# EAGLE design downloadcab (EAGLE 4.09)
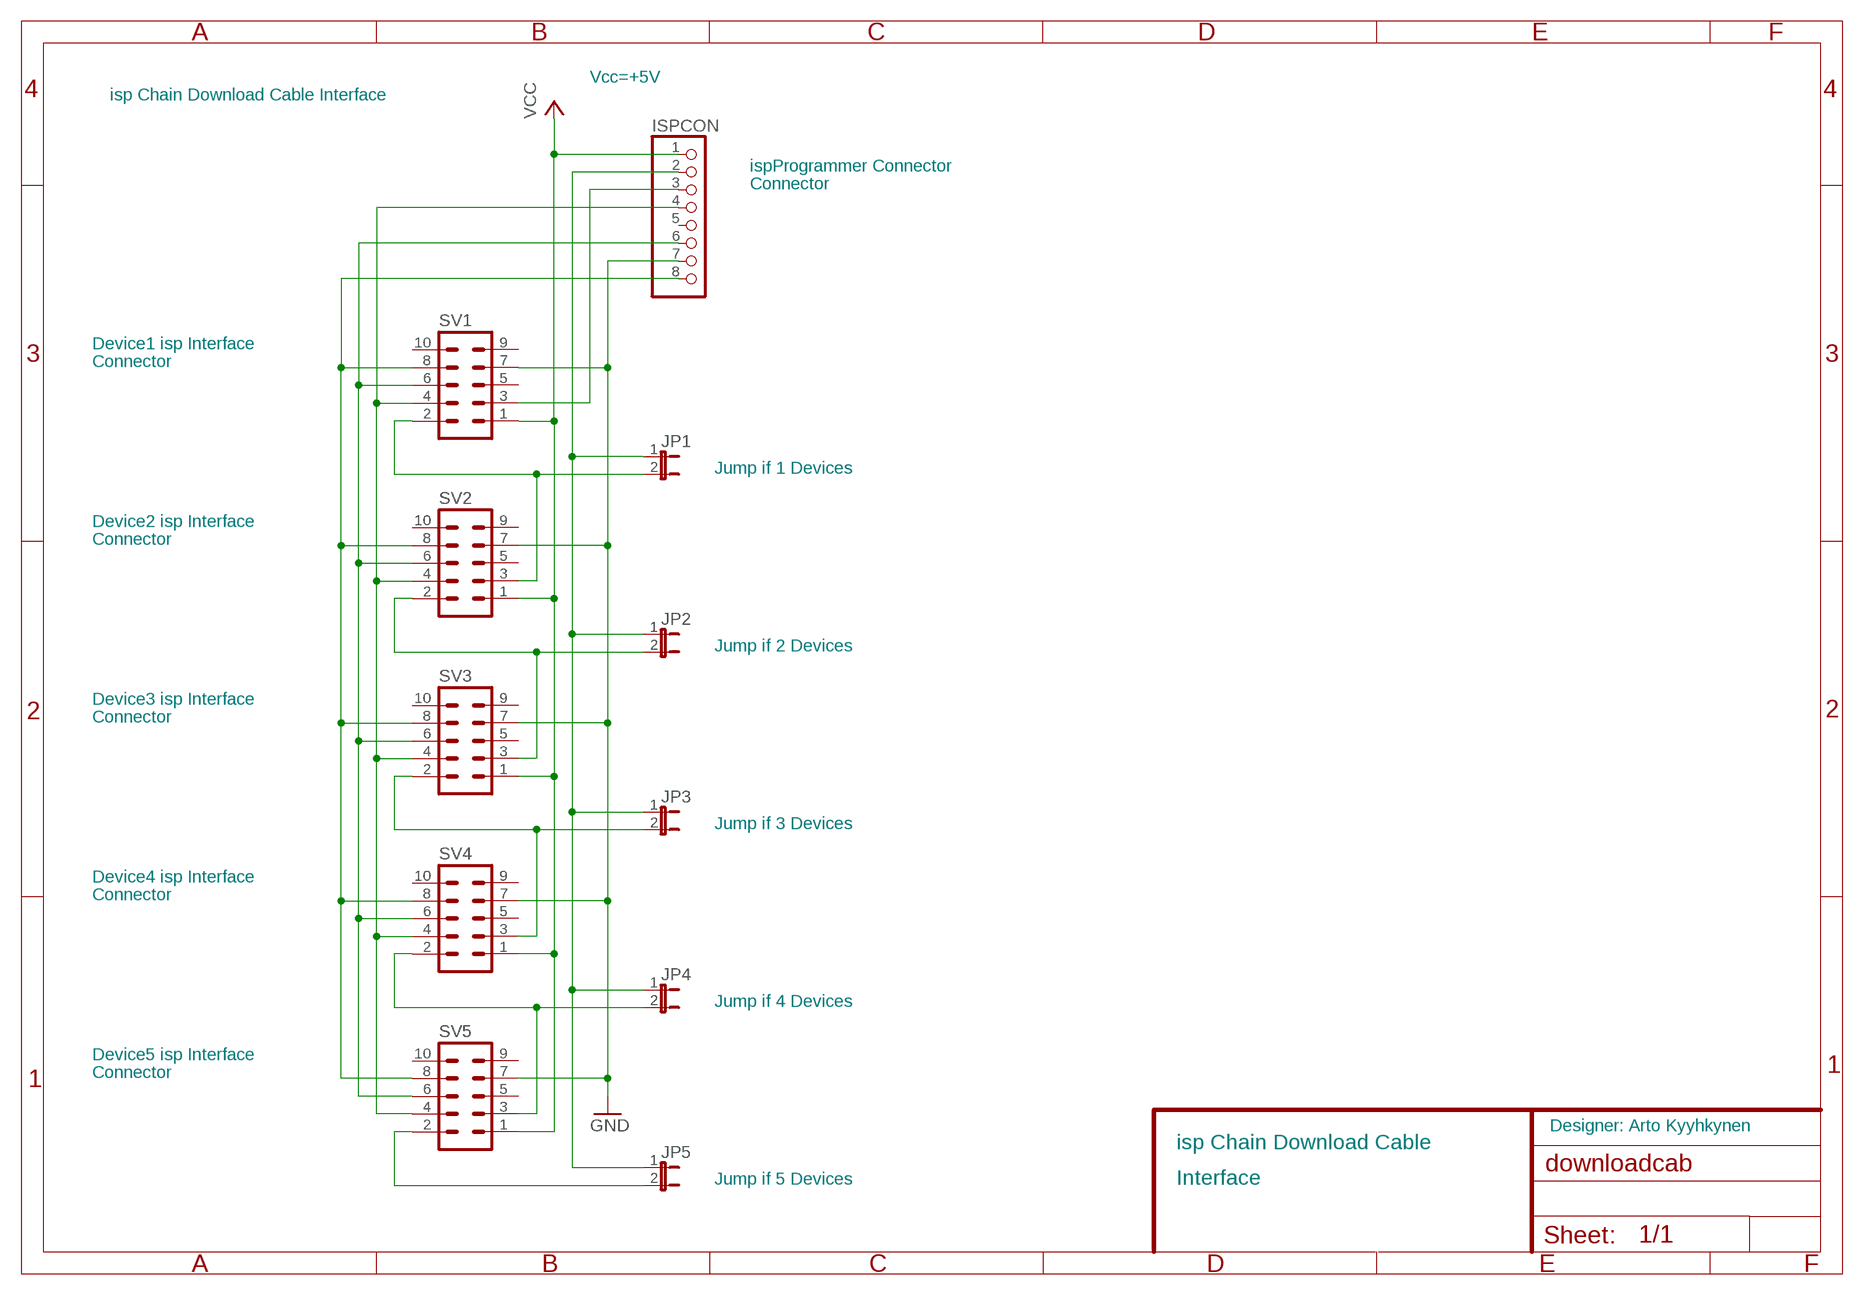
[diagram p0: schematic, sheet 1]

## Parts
ISPCON  PINHD-1X8  [1X08]
JP1  JP1E  [JP1]
JP2  JP1E  [JP1]
JP3  JP1E  [JP1]
JP4  JP1E  [JP1]
JP5  JP1E  [JP1]
SV1  ML10  [ML10]
SV2  ML10  [ML10]
SV3  ML10  [ML10]
SV4  ML10  [ML10]
SV5  ML10  [ML10]

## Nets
GND: ISPCON.7 SV1.7 SV2.7 SV3.7 SV4.7 SV5.7
ISPEN: ISPCON.4 SV1.4 SV2.4 SV3.4 SV4.4 SV5.4
MODE: ISPCON.6 SV1.6 SV2.6 SV3.6 SV4.6 SV5.6
SCLK: ISPCON.8 SV1.8 SV2.8 SV3.8 SV4.8 SV5.8
SDI: ISPCON.3 SV1.3
SDO: ISPCON.2 JP1.1 JP2.1 JP3.1 JP4.1 JP5.1
SDO1SDI1: JP1.2 SV1.2 SV2.3
SDO2SDI3: JP2.2 SV2.2 SV3.3
SDO3SDI4: JP3.2 SV3.2 SV4.3
SDO4SDI5: JP4.2 SV4.2 SV5.3
SDO5: JP5.2 SV5.2
VCC: ISPCON.1 SV1.1 SV2.1 SV3.1 SV4.1 SV5.1
Unconnected: ISPCON.5 SV1.5 SV1.9 SV1.10 SV2.5 SV2.9 SV2.10 SV3.5 SV3.9 SV3.10 SV4.5 SV4.9 SV4.10 SV5.5 SV5.9 SV5.10

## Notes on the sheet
- Vcc=+5V
- isp Chain Download Cable Interface
- ispProgrammer Connector
- Connector
- Device1 isp Interface
- Connector
- Jump if 1 Devices
- Device2 isp Interface
- Connector
- Jump if 2 Devices
- Device3 isp Interface
- Connector
- Jump if 3 Devices
- Device4 isp Interface
- Connector
- Jump if 4 Devices
- Device5 isp Interface
- Connector
- Designer: Arto Kyyhkynen
- isp Chain Download Cable
- Jump if 5 Devices | Interface

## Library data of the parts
ISPCON = pinhead:PINHD-1X8: PIN HEADER
JP1-JP5 = jumper:JP1E: JUMPER
SV1-SV5 = con-harting-ml:ML10: HARTING

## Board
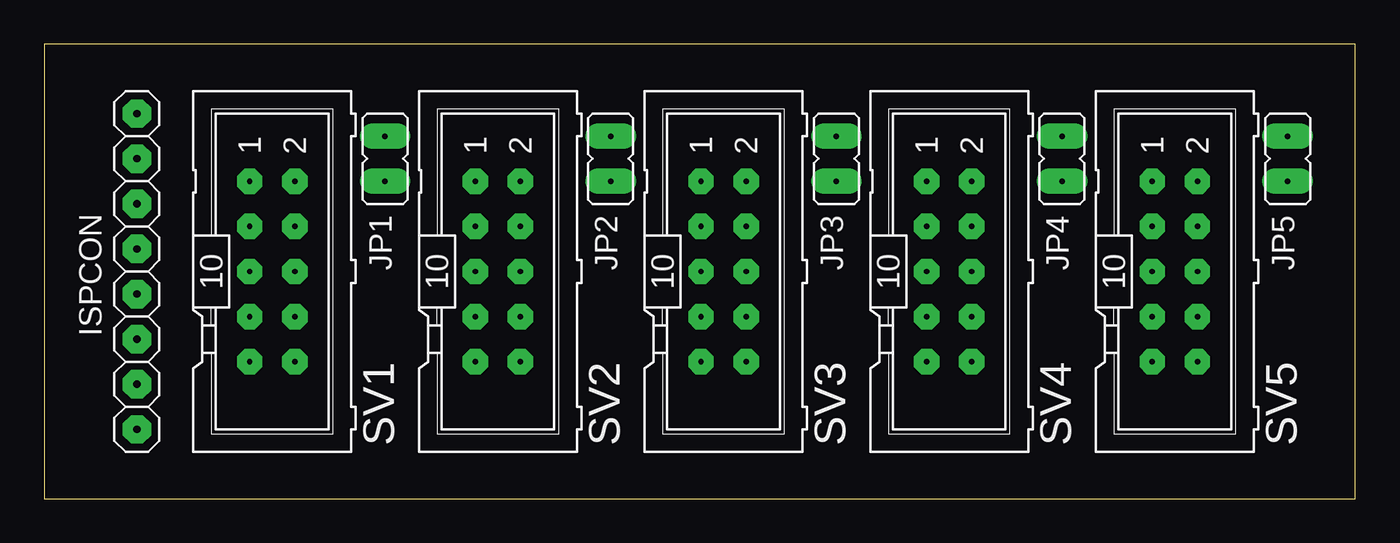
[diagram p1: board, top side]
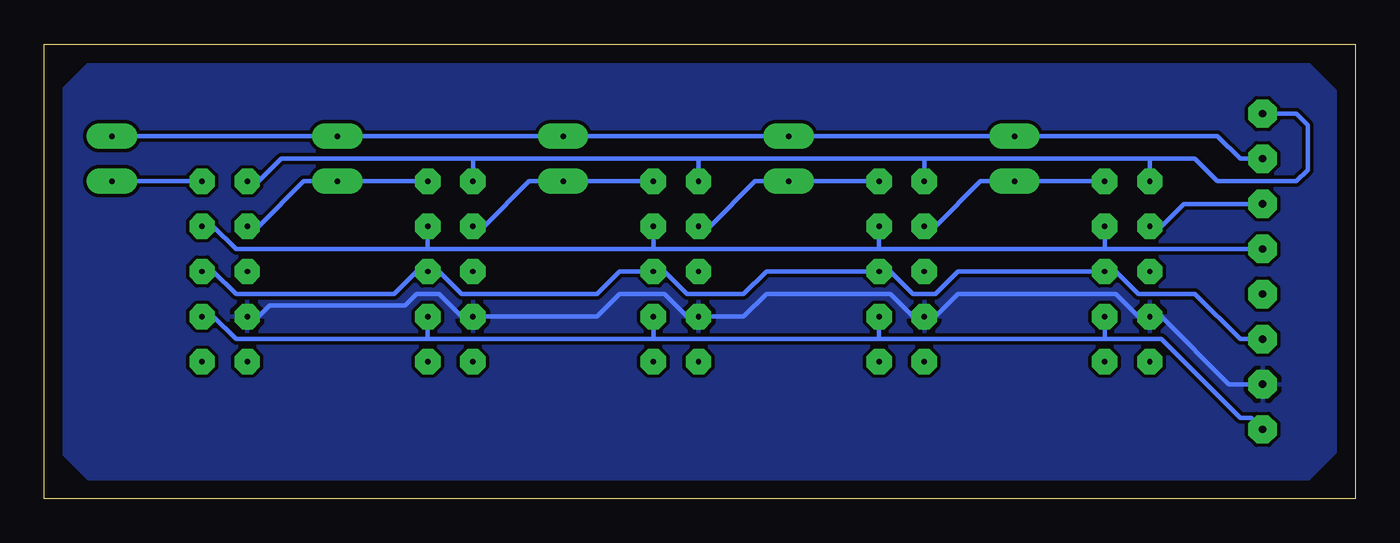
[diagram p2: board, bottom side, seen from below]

Size 73.77 x 25.58 mm. Coordinates in mm from the lower left corner, seen from the top.
Outline: 0,0 73.77,0 73.77,25.58 0,25.58 0,0
Copper layers used: Bottom

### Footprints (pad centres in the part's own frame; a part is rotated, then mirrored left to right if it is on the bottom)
SIL8 = drill 0.406 pad 1.6 octagon: 1 -8.89,0; 2 -6.35,0; 3 -3.81,0; 4 -1.27,0; 5 1.27,0; 6 3.81,0; 7 6.35,0; 8 8.89,0
JP1 = drill 0.305 pad 1.422 long: 1 0,-1.27; 2 0,1.27
ML10 = drill 0.305 pad 1.422 octagon: 1 -5.08,-1.27; 2 -5.08,1.27; 3 -2.54,-1.27; 4 -2.54,1.27; 5 0,-1.27; 6 0,1.27; 7 2.54,-1.27; 8 2.54,1.27; 9 5.08,-1.27; 10 5.08,1.27

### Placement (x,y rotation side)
ISPCON  [SIL8]  5.2,12.79 270 top
JP1  19.17,19.14 180 top
JP2  31.87,19.14 180 top
JP3  44.57,19.14 180 top
JP4  57.27,19.14 180 top
JP5  69.97,19.14 180 top
SV1  12.82,12.79 270 top
SV2  25.52,12.79 270 top
SV3  38.22,12.79 270 top
SV4  50.92,12.79 270 top
SV5  63.62,12.79 270 top

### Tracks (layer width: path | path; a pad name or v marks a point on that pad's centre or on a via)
GND
  Bottom 0.254: ISPCON.7 7.11,6.44 10.92,10.25 SV1.7 12.19,10.25 13.46,11.52 22.35,11.52 23.62,10.25 SV2.7 24.89,10.25 26.16,11.52 33.14,11.52 34.41,10.25 SV3.7 37.59,10.25 38.86,11.52 41.4,11.52 42.67,10.25 SV4.7 50.29,10.25 51.56,11.52 52.83,11.52 53.46,10.88 61.08,10.88 61.72,10.25 SV5.7
  pour Bottom: 1.14,22.95 2.66,24.47 71.24,24.47 72.77,22.95 72.77,2.63 71.24,1.1 2.66,1.1 1.14,2.63
ISPEN
  Bottom 0.254: 14.09,14.06 SV1.4 | ISPCON.4 14.09,14.06 | 26.79,14.06 SV2.4 | 14.09,14.06 26.79,14.06 | 39.49,14.06 SV3.4 | 26.79,14.06 39.49,14.06 | 52.19,14.06 SV4.4 | 39.49,14.06 52.19,14.06 | 52.19,14.06 62.99,14.06 64.26,15.33 SV5.4
MODE
  Bottom 0.254: SV5.6 64.26,12.79 62.99,11.52 54.1,11.52 52.83,12.79 SV4.6 51.56,12.79 50.29,11.52 42.67,11.52 41.4,12.79 SV3.6 38.86,12.79 37.59,11.52 34.41,11.52 33.14,12.79 SV2.6 26.16,12.79 24.89,11.52 23.62,11.52 22.35,12.79 SV1.6 13.46,12.79 12.19,11.52 9.01,11.52 6.47,8.98 ISPCON.6
SCLK
  Bottom 0.254: 14.09,8.98 SV1.8 | ISPCON.8 5.84,4.53 6.47,4.53 10.92,8.98 14.09,8.98 | 26.79,8.98 SV2.8 | 14.09,8.98 26.79,8.98 | 39.49,8.98 SV3.8 | 26.79,8.98 39.49,8.98 | 52.19,8.98 SV4.8 | 39.49,8.98 52.19,8.98 | 52.19,8.98 62.99,8.98 64.26,10.25 SV5.8
SDI
  Bottom 0.254: SV1.3 10.92,15.33 9.65,16.6 ISPCON.3
SDO
  Bottom 0.254: ISPCON.2 6.47,19.14 7.74,20.41 JP1.1 JP2.1 JP3.1 JP4.1 JP5.1
SDO1SDI1
  Bottom 0.254: SV2.3 23.62,15.33 21.08,17.87 JP1.2 SV1.2
SDO2SDI3
  Bottom 0.254: SV3.3 36.32,15.33 33.78,17.87 JP2.2 SV2.2
SDO3SDI4
  Bottom 0.254: SV4.3 49.02,15.33 46.48,17.87 JP3.2 SV3.2
SDO4SDI5
  Bottom 0.254: SV5.3 61.72,15.33 59.18,17.87 JP4.2 SV4.2
SDO5
  Bottom 0.254: SV5.2 JP5.2
VCC
  Bottom 0.254: 24.25,19.14 SV2.1 | 36.95,19.14 SV3.1 | 24.25,19.14 36.95,19.14 | 49.65,19.14 SV4.1 | 36.95,19.14 49.65,19.14 | 49.65,19.14 60.45,19.14 61.72,17.87 SV5.1 | 11.55,19.14 24.25,19.14 | 11.55,19.14 SV1.1 | 11.55,19.14 9.01,19.14 7.74,17.87 3.3,17.87 2.66,18.5 2.66,21.04 3.3,21.68 ISPCON.1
